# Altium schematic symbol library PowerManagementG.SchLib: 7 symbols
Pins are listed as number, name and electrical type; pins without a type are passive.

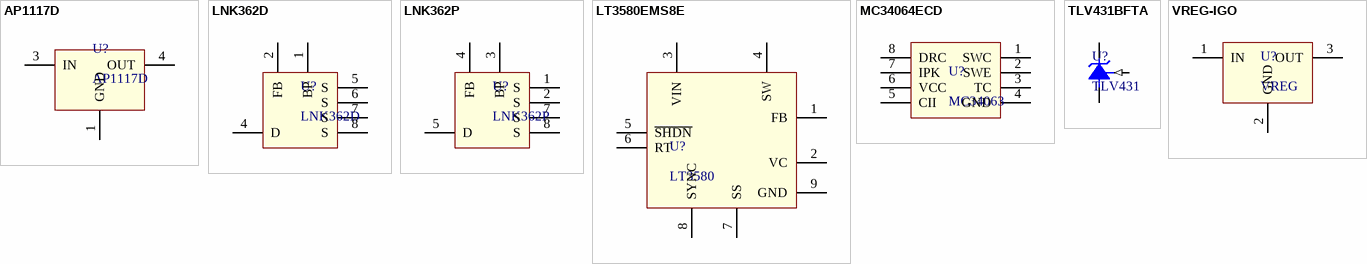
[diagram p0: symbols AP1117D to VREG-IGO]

## AP1117D
designator U?
Low Dropout Regulator
footprint TO-252 (D-PAK/TO-252-AA; 3 Leads (1 Cropped); Body 10.1 (inc. leads) x 6.6 mm (LxW max))
pins: 1 GND (power), 3 IN (power), 4 OUT (power)

## LNK362D
designator U?
Offline Flyback Switcher
footprint SOIC127P600-8N (SOIC, 8-Leads, Body 4.9x3.9mm, Pitch 1.27mm, IPC Medium Density)
pins: 1 BP, 2 FB, 4 D, 5 S, 6 S, 7 S, 8 S

## LNK362P
designator U?
Offline Flyback Switcher
footprint DIP-8 (DIP; 8 Leads; Row Spacing 7.62 mm; Pitch 2.54 mm)
pins: 1 S, 2 S, 3 BP, 4 FB, 5 D, 7 S, 8 S

## LT3580EMS8E
designator U?, comment LT3580
Boost/inverting DC/DC converter
pins: 1 FB, 2 VC, 3 VIN, 4 SW, 5 ~{SHDN}, 6 RT, 7 SS, 8 SYNC, 9 GND

## MC34064ECD
designator U?, comment MC34063
DC/DC converter
footprint SO8 (Small Outline; 8 Leads; Body Width 3.9 mm; Pitch 1.27 mm)
pins: 1 SWC, 2 SWE, 3 TC, 4 GND, 5 CII, 6 VCC, 7 IPK, 8 DRC

## TLV431BFTA
designator U?, comment TLV431
Adjustable shunt regulator
footprint SOT23-3N (SOT23, 3-Leads, Body 2.9x1.3mm, Pitch 0.95mm, Lead Span 2.5mm, IPC Medium Density)
pins: 1 REF (in), 2 CATHODE, 3 ANODE

## VREG-IGO
designator U?, comment VREG
Generic 3-terminal voltage regulator
footprint TO-220AB (TO, Thru-Hole, Vertical, Heatsink Mounted; 3 In-Line Leads; Pitch 2.54 mm)
pins: 1 IN, 2 GND, 3 OUT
